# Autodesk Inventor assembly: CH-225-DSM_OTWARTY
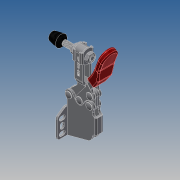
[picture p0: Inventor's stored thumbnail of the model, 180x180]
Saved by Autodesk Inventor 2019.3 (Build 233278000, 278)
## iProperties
Company: ·L?¤¤?
Created: 2010-06
Part Number: CH-225-DSM_OTWARTY
Material: Ogólny
Description: STEP AP203
Document SubType Name: Assembly
Designer: CADENGINEERING4
Sending System: SolidWorks 2005179
Preprocessor: SwSTEP 2.0
Title: CH-225-DSM.STEP
Author: ·L?¥Î?
Revision Number: ANY
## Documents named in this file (9)
- E:\STRONA\Horizontal toggle clamp\CH-225-DSM\CH-225-DSM_OTWARTY.iam
- E:\STRONA\Horizontal toggle clamp\CH-225-DSM\CH-FC-56212___.ipt
- E:\STRONA\Horizontal toggle clamp\CH-225-DSM\225-DSM-02___.ipt
- E:\STRONA\Horizontal toggle clamp\CH-225-DSM\225-D-04___.ipt
- E:\STRONA\Horizontal toggle clamp\CH-225-DSM\FW-516___.ipt
- E:\STRONA\Horizontal toggle clamp\CH-225-DSM\225-D-05___.ipt
- E:\STRONA\Horizontal toggle clamp\CH-225-DSM\56212-01___.ipt
- E:\STRONA\Horizontal toggle clamp\CH-225-DSM\225-D-03___.iam
- E:\STRONA\Horizontal toggle clamp\CH-225-DSM\225-DSM-01___.ipt
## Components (14 placed, 14 different names)
1. CH-FC-56212_??_1 — Równoległe:3, Zestawiające:1, Zestawiające:2, Zestawiające:4, Zestawiające:5, Zestawiające:9
2. 225-DSM-02_??_2 — Równoległe:1, Zestawiające:7, Zestawiające:8, Zestawiające:9, Zestawiające:21, Zestawiające:22, Zestawiające:25
3. 225-D-04_??_3 — Zestawiające:10, Zestawiające:11, Zestawiające:12
4. FW-516_??_4 — Równoległe:2, Zestawiające:4, Zestawiające:6, Zestawiające:7
5. 225-D-05_??_5 — Zestawiające:22, Zestawiające:26
6. 56212-01_??_6 — Zestawiające:5, Zestawiające:6
7. 225-D-03_??_7 [sub-assembly] — Zestawiające:17, Zestawiające:18, Zestawiające:19, Zestawiające:20, Zestawiające:23, Zestawiające:24, Przejściowe:1
8. 225-D-04_??_8 — Zestawiające:10, Zestawiające:11, Zestawiające:12, Zestawiające:13, Zestawiające:14, Zestawiające:17, Zestawiające:18
9. 225-D-05_??_9 — Zestawiające:19, Zestawiające:20
10. 225-DSM-01_??_10 — Zestawiające:13, Zestawiające:14, Zestawiające:15, Zestawiające:16, Zestawiające:21, Zestawiające:26, Przejściowe:1
11. FW-516_??_11 — Równoległe:1, Równoległe:2, Zestawiające:2, Zestawiające:3, Zestawiające:8
12. 225-D-05_??_12 — Zestawiające:23, Zestawiające:24, Zestawiające:25
13. 225-D-05_??_13 — Zestawiające:15, Zestawiające:16
14. 56212-01_??_15 — Równoległe:3, Zestawiające:1, Zestawiające:3
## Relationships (30: Mate 26, Flush 3, Transitional 1)
- Równoległe:1 [Flush]: 225-DSM-02_??_2 ↔ FW-516_??_11
- Równoległe:2 [Flush]: FW-516_??_4 ↔ FW-516_??_11
- Równoległe:3 [Flush]: CH-FC-56212_??_1 ↔ 56212-01_??_15
- Zestawiające:1 [Mate]: CH-FC-56212_??_1 ↔ 56212-01_??_15
- Zestawiające:2 [Mate]: CH-FC-56212_??_1 ↔ FW-516_??_11
- Zestawiające:3 [Mate]: FW-516_??_11 ↔ 56212-01_??_15
- Zestawiające:4 [Mate]: CH-FC-56212_??_1 ↔ FW-516_??_4
- Zestawiające:5 [Mate]: CH-FC-56212_??_1 ↔ 56212-01_??_6
- Zestawiające:6 [Mate]: FW-516_??_4 ↔ 56212-01_??_6
- Zestawiające:7 [Mate]: 225-DSM-02_??_2 ↔ FW-516_??_4
- Zestawiające:8 [Mate]: 225-DSM-02_??_2 ↔ FW-516_??_11
- Zestawiające:9 [Mate]: CH-FC-56212_??_1 ↔ 225-DSM-02_??_2
- Zestawiające:10 [Mate]: 225-D-04_??_3 ↔ 225-D-04_??_8
- Zestawiające:11 [Mate]: 225-D-04_??_3 ↔ 225-D-04_??_8
- Zestawiające:12 [Mate]: 225-D-04_??_3 ↔ 225-D-04_??_8
- Zestawiające:13 [Mate]: 225-D-04_??_8 ↔ 225-DSM-01_??_10
- Zestawiające:14 [Mate]: 225-D-04_??_8 ↔ 225-DSM-01_??_10
- Zestawiające:15 [Mate]: 225-DSM-01_??_10 ↔ 225-D-05_??_13
- Zestawiające:16 [Mate]: 225-DSM-01_??_10 ↔ 225-D-05_??_13
- Zestawiające:17 [Mate]: 225-D-03_??_7 ↔ 225-D-04_??_8
- Zestawiające:18 [Mate]: 225-D-03_??_7 ↔ 225-D-04_??_8
- Zestawiające:19 [Mate]: 225-D-03_??_7 ↔ 225-D-05_??_9
- Zestawiające:20 [Mate]: 225-D-03_??_7 ↔ 225-D-05_??_9
- Zestawiające:21 [Mate]: 225-DSM-02_??_2 ↔ 225-DSM-01_??_10
- Zestawiające:22 [Mate]: 225-DSM-02_??_2 ↔ 225-D-05_??_5
- Zestawiające:23 [Mate]: 225-D-03_??_7 ↔ 225-D-05_??_12
- Zestawiające:24 [Mate]: 225-D-03_??_7 ↔ 225-D-05_??_12
- Zestawiające:25 [Mate]: 225-DSM-02_??_2 ↔ 225-D-05_??_12
- Zestawiające:26 [Mate]: 225-D-05_??_5 ↔ 225-DSM-01_??_10
- Przejściowe:1 [Transitional]: 225-D-03_??_7 ↔ 225-DSM-01_??_10
